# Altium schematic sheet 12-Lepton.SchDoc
size A4
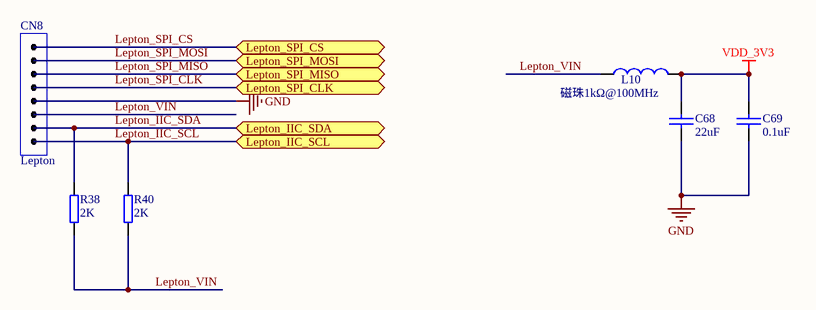
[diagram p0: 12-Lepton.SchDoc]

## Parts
C68  22uF  [C0805]
C69  0.1uF  [C0402]
CN8  Lepton  [SMD8(2.54)]
L10  磁珠1kΩ@100MHz  [L0603]
R38  2K  [R0402]
R40  2K  [R0402]

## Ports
Lepton_IIC_SCL (bidir), Lepton_IIC_SDA (bidir), Lepton_SPI_CLK (bidir), Lepton_SPI_CS (bidir), Lepton_SPI_MISO (bidir), Lepton_SPI_MOSI (bidir)

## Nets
GND: C68.2 C69.2 CN8.5
VDD_3V3: C68.1 C69.1 L10.2
Lepton_IIC_SCL: CN8.8 R40.2 ; port Lepton_IIC_SCL
Lepton_IIC_SDA: CN8.7 R38.2 ; port Lepton_IIC_SDA
Lepton_SPI_CLK: CN8.4 ; port Lepton_SPI_CLK
Lepton_SPI_CS: CN8.1 ; port Lepton_SPI_CS
Lepton_SPI_MISO: CN8.3 ; port Lepton_SPI_MISO
Lepton_SPI_MOSI: CN8.2 ; port Lepton_SPI_MOSI
Lepton_VIN: CN8.6 L10.1 R38.1 R40.1

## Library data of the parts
C68 C69 = 电容: Capacitor
CN8 = CN-8
L10 = 电感: Inductor
R38 R40 = 电阻Ω: Resistor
